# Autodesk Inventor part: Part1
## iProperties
Created: 2002-07
Part Number: Part1
Document SubType Name: Modeling
Designer: Administrator
Control State: 0
Master: False
Checked Out: False
Shininess: 64.0
Length Units: 11269
Angle Units: 11279
Time Units: 11290
Mass Units: 11283
Length Display Precision: 3
Angle Display Precision: 2
Density: 0.0
Volumn: 0.0
Area: 0.0
PropertySet Name: Model Information
Author: Administrator
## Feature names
1. Extrusion1
2. Extrusion2
3. Extrusion3
4. Extrusion4
5. Extrusion5
